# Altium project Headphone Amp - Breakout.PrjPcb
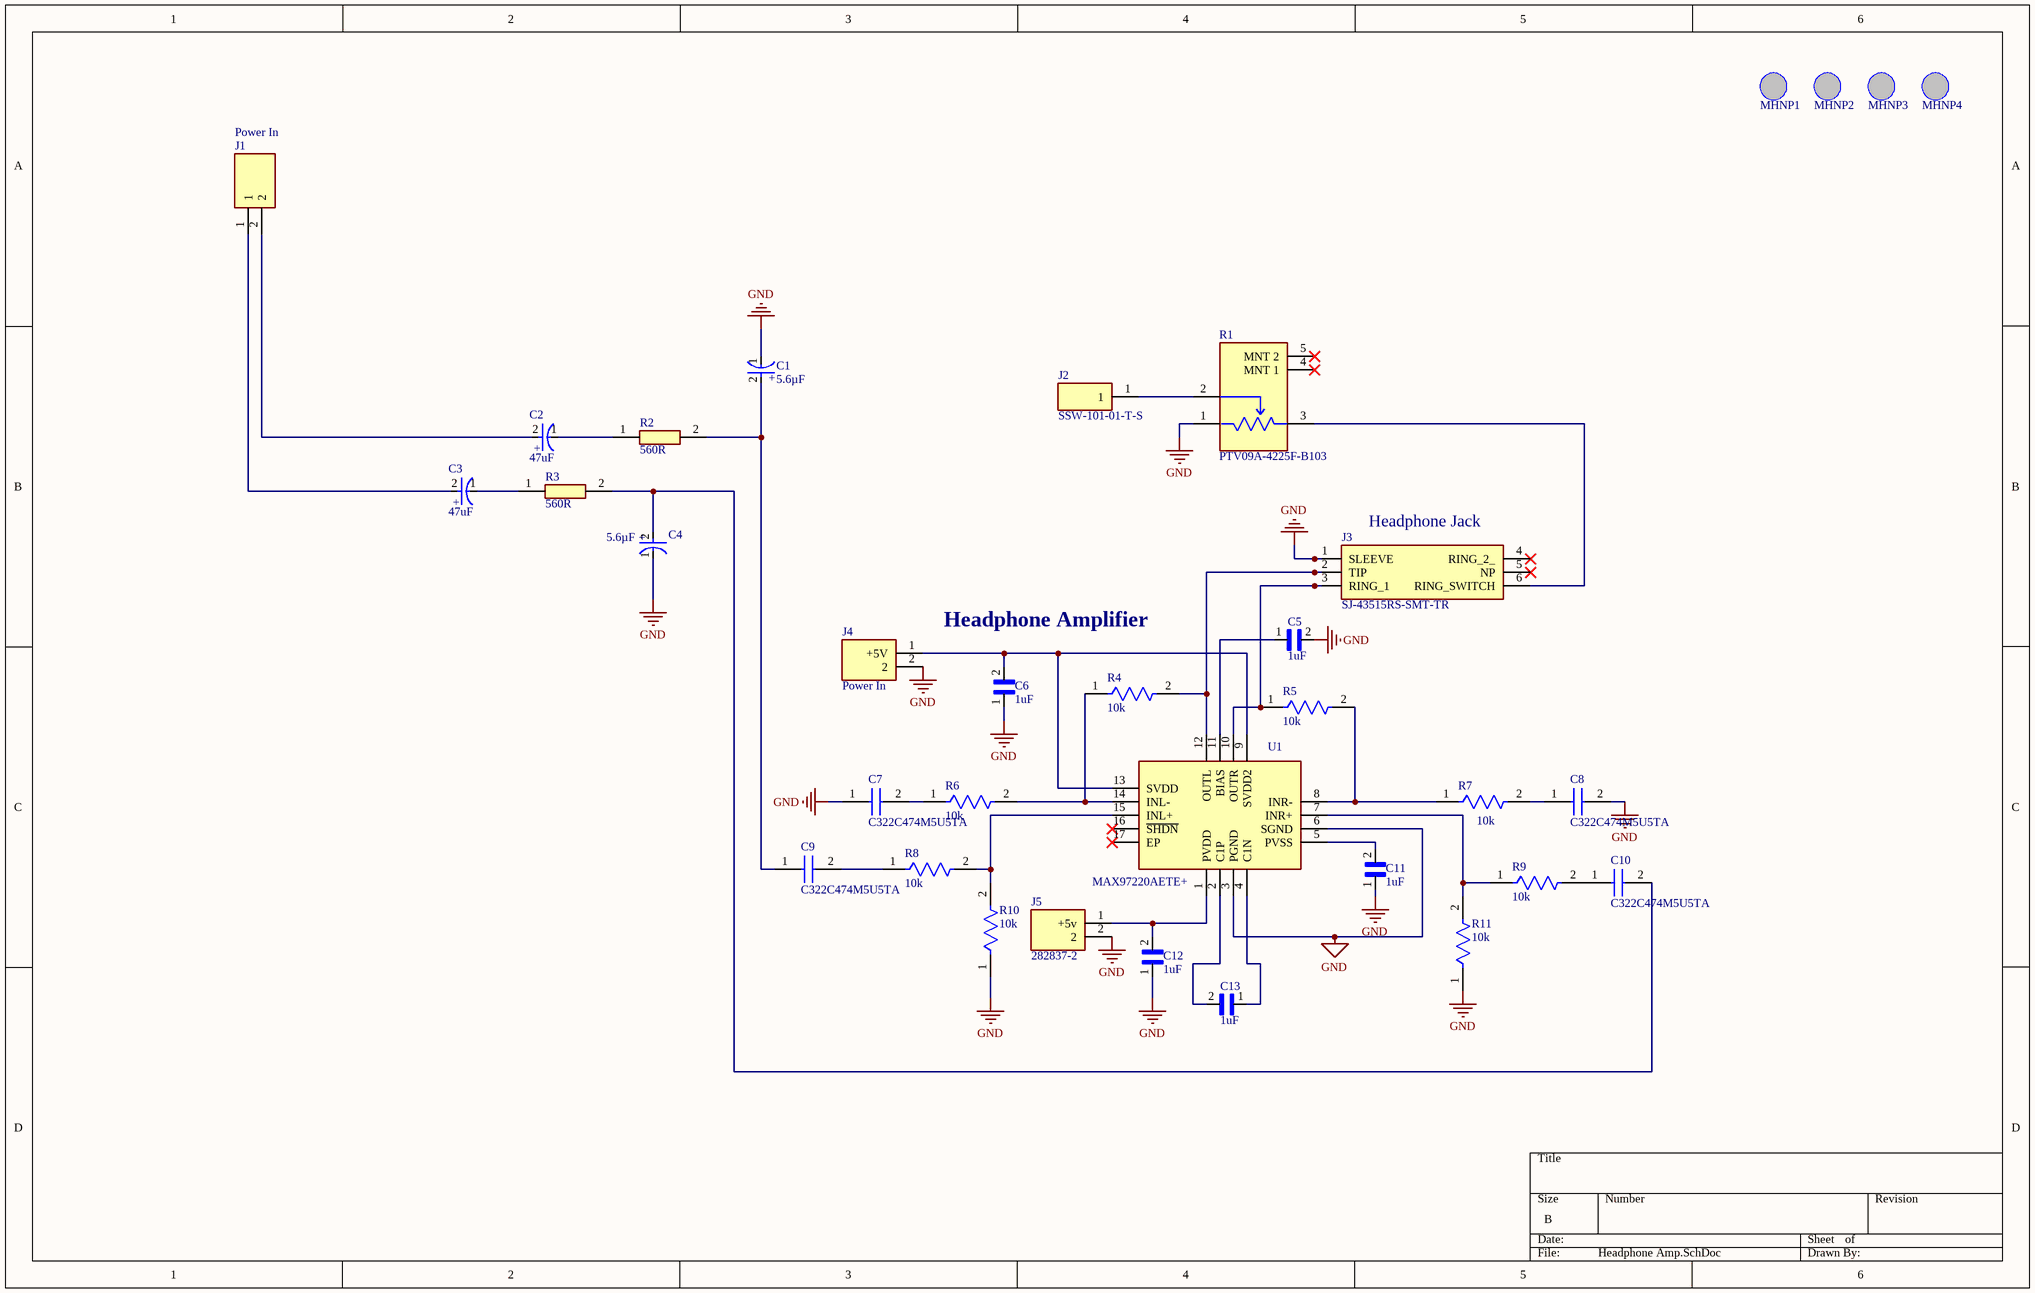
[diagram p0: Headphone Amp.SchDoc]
1 sheet, 34 parts. Net scope: global (net labels, ports and power ports of the same name join across sheets).
Board file: Headphone Amp Breakout.PcbDoc

## Sheet Headphone Amp.SchDoc
size B; SheetNumber: 1; SheetTotal: 1

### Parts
C1  5.6µF  [FP-RAD-TH-D_5_0_5-L_11_1-MFG]
C2  47uF  [FP-RAD-TH-D_5_0_5-L_11_1-MFG]
C3  47uF  [FP-RAD-TH-D_5_0_5-L_11_1-MFG]
C4  5.6µF  [FP-RAD-TH-D_5_0_5-L_11_1-MFG]
C5  1uF  [CAPRB250W50L550T350H600]
C6  1uF  [CAPRB250W50L550T350H600]
C7  C322C474M5U5TA  [C322C474M5U5TA]
C8  C322C474M5U5TA  [C322C474M5U5TA]
C9  C322C474M5U5TA  [C322C474M5U5TA]
C10  C322C474M5U5TA  [C322C474M5U5TA]
C11  1uF  [CAPRB250W50L550T350H600]
C12  1uF  [CAPRB250W50L550T350H600]
C13  1uF  [CAPRB250W50L550T350H600]
J1  Power In  [2828372]
J2  SSW-101-01-T-S  [SSW-101-XX-YYY-S]
J3  SJ-43515RS-SMT-TR  [SJ43515RSSMTTR]
J4  Power In  [2828372]
J5  282837-2  [2828372]
MHNP1  Mounting Hole Non-Plated 3.2mm  [MTHNP3P2MM]  (value not drawn)
MHNP2  Mounting Hole Non-Plated 3.2mm  [MTHNP3P2MM]  (value not drawn)
MHNP3  Mounting Hole Non-Plated 3.2mm  [MTHNP3P2MM]  (value not drawn)
MHNP4  Mounting Hole Non-Plated 3.2mm  [MTHNP3P2MM]  (value not drawn)
R1  PTV09A-4225F-B103  [FP-PTV09A-4-MFG]
R2  560R  [RESAD1800W60L720D270]
R3  560R  [RESAD1800W60L720D270]
R4  10k  [FP-RLR07-MFG]
R5  10k  [FP-RLR07-MFG]
R6  10k  [FP-RLR07-MFG]
R7  10k  [FP-RLR07-MFG]
R8  10k  [FP-RLR07-MFG]
R9  10k  [FP-RLR07-MFG]
R10  10k  [FP-RLR07-MFG]
R11  10k  [FP-RLR07-MFG]
U1  MAX97220AETE+  [QFN50P300X300X80-17N]

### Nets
GND: C1.1(C) C4.1(C) C5.2 C6.1 C7.1 C8.2 C11.1 C12.1 J3.1(SLEEVE) J4.2 J5.2 R1.1 R10.1 R11.1 U1.3(PGND) U1.6(SGND)
NetC1_2: C1.2(A) C9.1 R2.2
NetC2_1: C2.1(C) R2.1
NetC2_2: C2.2(A) J1.2
NetC3_1: C3.1(C) R3.1
NetC3_2: C3.2(A) J1.1
NetC4_2: C4.2(A) C10.2 R3.2
NetC5_1: C5.1 U1.11(BIAS)
NetC6_2: C6.2 J4.1(+5V) U1.9(SVDD2) U1.13(SVDD)
NetC7_2: C7.2 R6.1
NetC8_1: C8.1 R7.2
NetC9_2: C9.2 R8.1
NetC10_1: C10.1 R9.2
NetC11_2: C11.2 U1.5(PVSS)
NetC12_2: C12.2 J5.1(+5v) U1.1(PVDD)
NetC13_1: C13.1 U1.4(C1N)
NetC13_2: C13.2 U1.2(C1P)
NetJ2_1: J2.1 R1.2
NetJ3_2: J3.2(TIP) R4.2 U1.12(OUTL)
NetJ3_3: J3.3(RING_1) R5.1 U1.10(OUTR)
NetJ3_6: J3.6(RING_SWITCH) R1.3
NetR4_1: R4.1 R6.2 U1.14(INL-)
NetR5_2: R5.2 R7.1 U1.8(INR-)
NetR8_2: R8.2 R10.2 U1.15(INL+)
NetR9_1: R9.1 R11.2 U1.7(INR+)

Not connected (* = marked no-connect by the designer): J3 4(RING_2_)* 5(NP)*; R1 4(MNT_1)* 5(MNT_2)*; U1 16(~{SHDN})* 17(EP)*

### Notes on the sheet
- (near J3) Headphone Jack
- Design filters based on bandwidth of signal and sampling frequency. Filters may also be redundant.
- Headphone Amplifier
- Why are BIAS and PVSS tied together?
- Circuitry is a combination of mic amplifiers datasheet and ADAU dev kit schematic. Tests need to be done to verify if +L and +R are fed correctly

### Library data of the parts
C1 C4 = CMP-05427-001597-1: Aluminum Electrolytic Capacitors (Radial Lead Type) AEC-Q200 Qualified 5.6uF ±20% 100V; Impedance: 4.1R; Ripple Current: 80mA; Leakage Current: 3uA; Lead Diameter: 0.5mm; Life (Hours): 1000Hour
C2 = CMP-05427-000413-1: Aluminum Electrolytic Capacitors (Radial Lead Type) AEC-Q200 Qualified 47uF ±20% 35V EEUHD1V470; Polarity: Polar; Ripple Current (AC): 90mA; Life (Hours): 1000Hour; Lead/Base Style: Straight; Lead Diameter: 0.5mm
C3 = CMP-05427-000413-1: Aluminum Electrolytic Capacitors (Radial Lead Type) AEC-Q200 Qualified 47uF ±20% 35V 47uF EEUHD1V470; Polarity: Polar; Ripple Current (AC): 90mA; Life (Hours): 1000Hour; Lead/Base Style: Straight; Lead Diameter: 0.5mm
C5 C6 C11-C13 = CMP-030-000003-1: 1 ÂµF Â±10% 25V Ceramic Capacitor X7R Radial; MP: FA16X7R1E105KNU06; MF: TDK
C7-C10 = C322C474M5U5TA: Capacitor; Manufacturer_Name: KEMET
J1 J5 = 282837-2: Connector; Manufacturer_Name: TE Connectivity
J2 = SSW-101-01-T-S: Connector; Manufacturer_Name: SAMTEC
J3 = CMP-004-000000-1: Connector; Manufacturer_Name: Same Sky
J4 = 282837-2: Connector / 282837-2; Manufacturer_Name: TE Connectivity
MHNP1-MHNP4 = MHNP3P2MM: Mounting Hole Non-Plated 3.2mm drill hole
R1 = CMP-07234-000052-1: POT 10K OHM 1/20W CARBON LINEAR; Power Rating: 50mW; Number of Gangs: 1; Hole Diameter: 9.1mm; Actuator Diameter: 0.236inch; Resistance Tolerance: 20%; Resistance: 10kR; Actuator Length: 0.984inch
R2 R3 = H8560RFYA: Resistor; Manufacturer_Name: TE Connectivity
R4-R11 = CMP-00030-39449004-1: RLR07C1002FSB14 Fixed Resistor, Metal Film, 0.25W, 10000ohm, 250V, 1% +/-Tol, 100ppm/Cel, Through Hole Mount; Power Rating: 250mW; Lead Diameter: 640µm; Wire/Cable Diameter: 50.8µm; Lead Length: 38.1mm; Resistance: 10kΩ; Temperature Coefficient: 100ppm/°C
U1 = MAX97220AETE+: Integrated Circuit; Manufacturer_Name: Analog Devices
